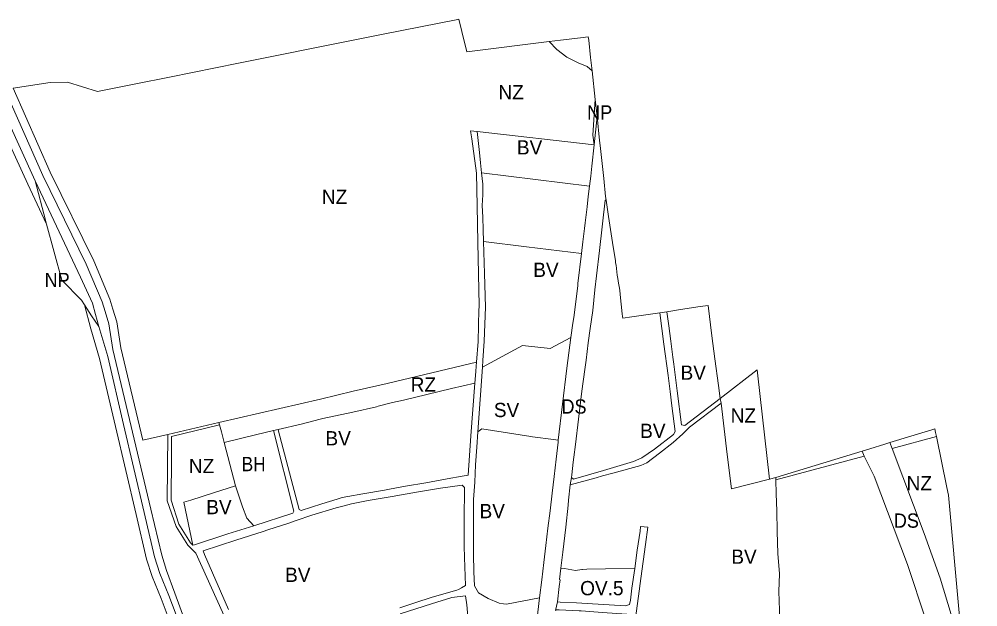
# Model space of a CAD drawing. Extents: x -650451 to -642268, y -1075216 to -1066610.
# Drawn here: x -648639 to -647831, y -1067105 to -1066610 of the extents above; entities that cross this region are included whole.
import ezdxf

# ---------------------------------------------------------------- set-up
doc = ezdxf.new("R2010")
doc.units = 0
doc.header["$LTSCALE"] = 4.8
for name, color, linetype, lineweight in [('1', 7, 'Continuous', 13), ('11', 7, 'Continuous', 13), ('15', 7, 'Continuous', 13), ('19', 7, 'Continuous', 13), ('24', 7, 'Continuous', 13), ('3', 7, 'Continuous', 13), ('45', 7, 'Continuous', 13), ('46', 7, 'Continuous', 13), ('48', 7, 'Continuous', 13), ('6', 7, 'Continuous', 13)]:
    doc.layers.add(name, color=color, linetype=linetype, lineweight=lineweight)
doc.layers.add('62', color=7, linetype='Continuous')

msp = doc.modelspace()

# ---------------------------------------------------------------- linework, layer by layer
at = {"layer": '1'}
for points in [[(-648466.26, -1066967), (-648439.91, -1066960.58), (-648424.66, -1066956.87)], [(-648424.66, -1066956.87), (-648407.6, -1067024.83), (-648408.46, -1067026.54), (-648441.28, -1067037.04)], [(-648441.28, -1067037.04), (-648447.23, -1067030.63), (-648450.92, -1067021.17), (-648456.62, -1067003.59), (-648466.26, -1066967)]]:
    msp.add_lwpolyline(points, dxfattribs=at)
at = {"layer": '11'}
for points in [[(-648185.48, -1067101.2), (-648183.92, -1067088.24), (-648183.16, -1067082.6), (-648183.67, -1067082.49), (-648182.63, -1067072.9)], [(-648120.26, -1067073.08), (-648122.67, -1067089.62), (-648123.95, -1067099.92), (-648124.74, -1067103.48), (-648128.02, -1067104.53), (-648160.45, -1067102.58), (-648169.34, -1067102.04), (-648183.06, -1067101.36), (-648185.48, -1067101.2)], [(-648182.63, -1067072.9), (-648179.46, -1067073.12), (-648170.29, -1067074.73), (-648164.79, -1067073.83), (-648164.38, -1067073.82), (-648160.6, -1067073.75), (-648144.93, -1067073.47), (-648120.26, -1067073.08)]]:
    msp.add_lwpolyline(points, dxfattribs=at)
at = {"layer": '15'}
for p, q in [((-648174.67, -1067002.55), (-648173.67, -1066996.46)), ((-648187.15, -1067108.56), (-648185.48, -1067101.2))]:
    msp.add_line(p, q, dxfattribs=at)
for points in [[(-648192.53, -1066629.28), (-648182.76, -1066628.07), (-648165.91, -1066625.97), (-648159.46, -1066625.17), (-648159.14, -1066628.07), (-648157.55, -1066642.67), (-648156.34, -1066653.83)], [(-648156.34, -1066653.83), (-648160.48, -1066650.28), (-648167.88, -1066647.1), (-648177.6, -1066642.24), (-648185.98, -1066636.03), (-648192.53, -1066629.28)], [(-648253.65, -1066899.2), (-648252.33, -1066881.94), (-648251.56, -1066854.93), (-648251.5, -1066852.88), (-648251.47, -1066851.6), (-648252.6, -1066798.46), (-648252.97, -1066767.53), (-648253.6, -1066739.98), (-648257.68, -1066711.07), (-648258.64, -1066704.31), (-648253.23, -1066704.92)], [(-648253.23, -1066704.92), (-648251.26, -1066722.82), (-648250.35, -1066731.5), (-648249.44, -1066739.8)], [(-648249.44, -1066739.8), (-648248.34, -1066749.33), (-648248.43, -1066758.34), (-648248.77, -1066767.43)], [(-648248.77, -1066767.43), (-648248.448, -1066777.212), (-648248.09, -1066787.96), (-648247.78, -1066797.53)], [(-648247.78, -1066797.53), (-648246.93, -1066824.58), (-648246.12, -1066852.86), (-648247.22, -1066881.51), (-648248.34, -1066897.92), (-648248.72, -1066903.46), (-648252.45, -1066958.01)], [(-648173.67, -1066996.46), (-648171.97, -1066997.89), (-648146.71, -1066990.48), (-648121.36, -1066982.96), (-648114.45, -1066979.9), (-648103.8, -1066972.73), (-648087.66, -1066960.29), (-648086.26, -1066957.66), (-648089.01, -1066936.01), (-648090.54, -1066924.13), (-648092.29, -1066910.62), (-648095.81, -1066884.07), (-648099.18, -1066857.71), (-648093.27, -1066856.88)], [(-648093.27, -1066856.88), (-648091.68, -1066868.78), (-648089.99, -1066881.53), (-648088.27, -1066895.01), (-648087.52, -1066900.96), (-648084.63, -1066923.32), (-648080.84, -1066952.2), (-648078.14, -1066952.77), (-648048.43, -1066929.91), (-648047.56, -1066933.82)], [(-648254.98, -1066916.96), (-648254.25, -1066907.07), (-648253.92, -1066902.78), (-648253.65, -1066899.2)], [(-648420.84, -1066956), (-648420.78, -1066956.25), (-648402.99, -1067023.54), (-648401.5, -1067024.22), (-648383.91, -1067018.53), (-648371.19, -1067014.59), (-648366.97, -1067013.34), (-648362.15, -1067012.49), (-648349.43, -1067010.23), (-648331.09, -1067007), (-648326.96, -1067006.27), (-648313.35, -1067003.85), (-648296.31, -1067000.87), (-648278.46, -1066997.56), (-648265.67, -1066995.28), (-648260.8, -1066994.4), (-648258.32, -1066961.37), (-648254.98, -1066916.96)], [(-648047.56, -1066933.82), (-648074.11, -1066953.96), (-648079.73, -1066959.7), (-648087.94, -1066966.99), (-648099.61, -1066975.99), (-648110.16, -1066984.14), (-648115.2, -1066986.34), (-648138.9, -1066992.73), (-648147.52, -1066995.06), (-648152.91, -1066996.6), (-648167.52, -1067000.71), (-648174.67, -1067002.55)], [(-648513.842, -1066960.243), (-648470.68, -1066950.24), (-648470.17, -1066952.17)], [(-648470.17, -1066952.17), (-648510.57, -1066961.9), (-648510.61, -1066966.55), (-648510.69, -1066976.8), (-648510.71, -1066978.63), (-648511.02, -1067015.58), (-648504.44, -1067035.85), (-648494.58, -1067051.41), (-648492.67, -1067053.5)], [(-648441.28, -1067037.04), (-648408.46, -1067026.54), (-648407.6, -1067024.83), (-648424.66, -1066956.87), (-648420.84, -1066956)], [(-648447.66, -1067153.25), (-648467.56, -1067110.02), (-648490.23, -1067060.06), (-648496.87, -1067053.5), (-648506.78, -1067037.81), (-648514.38, -1067016.2), (-648513.842, -1066960.243)], [(-648252.45, -1066958.01), (-648253.35, -1066970.9), (-648254.43, -1066985.75), (-648255.15, -1067000.4), (-648256.12, -1067014.87), (-648256.12, -1067029.58), (-648256.25, -1067046.57), (-648256.18, -1067061.04), (-648255.91, -1067075.83), (-648255.49, -1067087.62), (-648251.85, -1067093.58), (-648243.79, -1067098.45), (-648234.58, -1067102.41), (-648230.86, -1067102.82), (-648228.38, -1067103.09), (-648200.58, -1067097.82)], [(-648318.38, -1067106.37), (-648305.53, -1067102.05), (-648290.96, -1067097.14), (-648270.3, -1067091.29), (-648268.79, -1067090.68), (-648266.35, -1067089.33), (-648262.82, -1067087.38), (-648263.67, -1067063.83), (-648264.11, -1067054.38), (-648264, -1067049.27), (-648263.98, -1067032.43), (-648263.75, -1067004.82), (-648265.85, -1067002.98), (-648284.03, -1067005.42), (-648304.31, -1067008.7), (-648324.83, -1067012.36), (-648344.88, -1067015.79), (-648358.92, -1067018.69), (-648365.27, -1067020.27), (-648371.77, -1067022.03), (-648392.27, -1067028.16), (-648405.7, -1067032.78), (-648412.55, -1067035.13), (-648429.59, -1067040.65), (-648433.28, -1067041.85), (-648456.52, -1067049.26), (-648483.84, -1067058.1), (-648482.9, -1067061.25), (-648462.48, -1067107.73)], [(-648492.67, -1067053.5), (-648491.28, -1067053.05), (-648463.12, -1067044.04), (-648441.28, -1067037.04)], [(-648120.26, -1067073.08), (-648118.18, -1067057.64), (-648115.89, -1067041.73), (-648115.37, -1067037.82), (-648109.4, -1067038.4), (-648111.32, -1067052.86), (-648113.21, -1067067.35), (-648115.19, -1067081.63), (-648117.16, -1067096.34), (-648119.2, -1067110.85), (-648121, -1067125.08), (-648122.95, -1067140.69), (-648123.31, -1067144.17), (-648129.51, -1067143.6), (-648127.29, -1067128.4), (-648126.24, -1067112.71), (-648127.23, -1067111.47), (-648147.53, -1067110.1), (-648165.4, -1067108.88), (-648167.25, -1067108.76), (-648183.98, -1067107.89), (-648186.54, -1067107.89), (-648187.15, -1067108.56)], [(-648185.48, -1067101.2), (-648183.06, -1067101.36), (-648169.34, -1067102.04), (-648160.45, -1067102.58), (-648128.02, -1067104.53), (-648124.74, -1067103.48), (-648123.95, -1067099.92), (-648122.67, -1067089.62), (-648120.26, -1067073.08)], [(-648260.23, -1067123.43), (-648261.9, -1067103.74), (-648262.98, -1067096.21), (-648274.32, -1067097.65), (-648291.72, -1067102.95), (-648317.87, -1067111.36)], [(-648200.58, -1067097.82), (-648203.67, -1067124.43), (-648204.77, -1067124.3)]]:
    msp.add_lwpolyline(points, dxfattribs=at)
for points in [[(-647905.28, -1066967.07), (-647869.93, -1066956.27), (-647867.46, -1066955.52), (-647866.83, -1066958.62), (-647866.14, -1066961.98), (-647903.5, -1066972.05)], [(-648001.56, -1066996.48), (-647928.82, -1066974.26), (-647927.03, -1066978.39), (-648001.46, -1066998.45)]]:
    msp.add_lwpolyline(points, close=True, dxfattribs=at)
at = {"layer": '19'}
msp.add_line((-648252.45, -1066958.01), (-648248.72, -1066903.46), dxfattribs=at)
for points in [[(-648248.72, -1066903.46), (-648214.86, -1066885.27), (-648191.69, -1066887.78), (-648174.1, -1066878.6)], [(-648174.1, -1066878.6), (-648177.43, -1066904.42), (-648184.76, -1066965.08)], [(-648184.76, -1066965.08), (-648188.76, -1066964.53), (-648206.52, -1066962.1), (-648207.96, -1066961.91), (-648249.08, -1066955.37), (-648252.45, -1066958.01)]]:
    msp.add_lwpolyline(points, dxfattribs=at)
at = {"layer": '24'}
for points in [[(-648158.49, -1066750.93), (-648157.46, -1066742.51), (-648156.44, -1066734.09), (-648154.59, -1066716.19), (-648152.14, -1066692.48)], [(-648152.14, -1066692.48), (-648149.94, -1066712.67), (-648149.5, -1066716.77), (-648146.47, -1066744.59), (-648144.84, -1066759.62), (-648144.49, -1066762.87)], [(-648160.51, -1066768.4), (-648159.66, -1066759.8), (-648158.49, -1066750.93)], [(-648144.49, -1066762.87), (-648145.22, -1066762.7), (-648150.16, -1066805.32), (-648152.62, -1066826.56), (-648153.91, -1066838.34), (-648155.78, -1066855.77), (-648157.88, -1066871), (-648159.53, -1066882.99), (-648161.34, -1066897.51), (-648162.34, -1066905.6), (-648164.78, -1066923.69), (-648166.53, -1066937.71), (-648167.74, -1066947.37), (-648170.38, -1066968.61), (-648171.57, -1066979.24), (-648172.1, -1066983.53), (-648173.44, -1066994.3), (-648173.67, -1066996.46), (-648174.67, -1067002.55)], [(-648165.33, -1066807.74), (-648164.14, -1066797.98), (-648162.8, -1066786.8), (-648162.01, -1066781.79), (-648161.58, -1066777.41), (-648160.51, -1066768.4)], [(-648174.1, -1066878.6), (-648172.44, -1066866.5), (-648171.79, -1066861.74), (-648168.38, -1066834.94), (-648168.15, -1066833.1), (-648165.33, -1066807.74)], [(-648184.76, -1066965.08), (-648177.43, -1066904.42), (-648174.1, -1066878.6)], [(-648200.58, -1067097.82), (-648198.61, -1067082.61), (-648196.96, -1067068.06), (-648195.18, -1067053.61), (-648193.5, -1067039.02), (-648191.7, -1067024.43), (-648189.94, -1067009.79), (-648188.31, -1066995.56), (-648186.65, -1066980.99), (-648184.94, -1066966.58), (-648184.76, -1066965.08)], [(-647928.82, -1066974.26), (-647922.2, -1066972.24), (-647909.51, -1066968.36), (-647905.28, -1066967.07), (-647903.5, -1066972.05)], [(-647903.5, -1066972.05), (-647876.57, -1067043.5), (-647863.04, -1067081.36), (-647853.65, -1067111.91), (-647844.3, -1067141.25)], [(-647831.28, -1067280.69), (-647842.17, -1067239.18), (-647855.42, -1067190.8), (-647874.95, -1067116.23), (-647890.64, -1067069.73), (-647918.62, -1066995.29), (-647927.03, -1066978.39), (-647928.82, -1066974.26)], [(-648174.67, -1067002.55), (-648176.09, -1067015.48), (-648176.55, -1067019.65), (-648178.5, -1067038.43), (-648180.99, -1067059.37), (-648182.63, -1067072.9)], [(-648182.63, -1067072.9), (-648183.67, -1067082.49), (-648183.16, -1067082.6), (-648183.92, -1067088.24), (-648185.48, -1067101.2), (-648187.15, -1067108.56)], [(-648204.77, -1067124.3), (-648203.67, -1067124.43), (-648200.58, -1067097.82)]]:
    msp.add_lwpolyline(points, dxfattribs=at)
at = {"layer": '3'}
msp.add_line((-648253.23, -1066704.92), (-648154.59, -1066716.19), dxfattribs=at)
for points in [[(-648249.44, -1066739.8), (-648250.35, -1066731.5), (-648251.26, -1066722.82), (-648253.23, -1066704.92)], [(-648154.59, -1066716.19), (-648156.44, -1066734.09), (-648157.46, -1066742.51), (-648158.49, -1066750.93), (-648249.44, -1066739.8)], [(-648173.67, -1066996.46), (-648173.44, -1066994.3), (-648172.1, -1066983.53), (-648171.57, -1066979.24), (-648170.38, -1066968.61), (-648167.74, -1066947.37), (-648166.53, -1066937.71), (-648164.78, -1066923.69), (-648162.34, -1066905.6), (-648161.34, -1066897.51), (-648159.53, -1066882.99), (-648157.88, -1066871), (-648155.78, -1066855.77), (-648153.91, -1066838.34), (-648152.62, -1066826.56), (-648150.16, -1066805.32), (-648145.22, -1066762.7), (-648144.49, -1066762.87)], [(-648144.49, -1066762.87), (-648142.37, -1066776.69), (-648138.49, -1066802.1), (-648137.73, -1066807.04), (-648136.68, -1066813.92), (-648136.42, -1066815.56), (-648136.1, -1066817.55), (-648135.01, -1066825.88), (-648134.7, -1066828.69), (-648134.53, -1066828.66), (-648134.17, -1066831.05), (-648132.96, -1066838.67), (-648132.62, -1066842.35), (-648130.92, -1066858.62), (-648130.56, -1066860.71), (-648130.3, -1066862.19), (-648122.93, -1066861.23), (-648103.17, -1066858.32), (-648099.18, -1066857.71)], [(-648248.72, -1066903.46), (-648248.34, -1066897.92), (-648247.22, -1066881.51), (-648246.12, -1066852.86), (-648246.93, -1066824.58), (-648247.78, -1066797.53)], [(-648247.78, -1066797.53), (-648211.58, -1066802.18), (-648165.33, -1066807.74)], [(-648165.33, -1066807.74), (-648168.15, -1066833.1), (-648168.38, -1066834.94), (-648171.79, -1066861.74), (-648172.44, -1066866.5), (-648174.1, -1066878.6)], [(-648093.27, -1066856.88), (-648081.68, -1066855.07), (-648065.35, -1066852.43), (-648058.56, -1066851.51), (-648055.39, -1066877.11), (-648052.75, -1066896.43), (-648049.86, -1066918.87), (-648048.43, -1066929.91)], [(-648099.18, -1066857.71), (-648095.81, -1066884.07), (-648092.29, -1066910.62), (-648090.54, -1066924.13), (-648089.01, -1066936.01), (-648086.26, -1066957.66), (-648087.66, -1066960.29), (-648103.8, -1066972.73), (-648114.45, -1066979.9), (-648121.36, -1066982.96), (-648146.71, -1066990.48), (-648171.97, -1066997.89), (-648173.67, -1066996.46)], [(-648048.43, -1066929.91), (-648078.14, -1066952.77), (-648080.84, -1066952.2), (-648084.63, -1066923.32), (-648087.52, -1066900.96), (-648088.27, -1066895.01), (-648089.99, -1066881.53), (-648091.68, -1066868.78), (-648093.27, -1066856.88)], [(-648174.1, -1066878.6), (-648191.69, -1066887.78), (-648214.86, -1066885.27), (-648248.72, -1066903.46)], [(-648420.84, -1066956), (-648401.5, -1066951.58), (-648385.27, -1066947.45), (-648383.04, -1066946.88), (-648357.9, -1066941.49), (-648338.01, -1066936.82), (-648336.45, -1066936.45), (-648324.34, -1066933.25), (-648315.22, -1066931.2), (-648295.55, -1066926.56), (-648274.7, -1066921.51), (-648254.98, -1066916.96)], [(-648254.98, -1066916.96), (-648258.32, -1066961.37), (-648260.8, -1066994.4), (-648265.67, -1066995.28), (-648278.46, -1066997.56), (-648296.31, -1067000.87), (-648313.35, -1067003.85), (-648326.96, -1067006.27), (-648331.09, -1067007), (-648349.43, -1067010.23), (-648362.15, -1067012.49), (-648366.97, -1067013.34), (-648371.19, -1067014.59), (-648383.91, -1067018.53), (-648401.5, -1067024.22), (-648402.99, -1067023.54), (-648420.78, -1066956.25), (-648420.84, -1066956)], [(-648174.67, -1067002.55), (-648167.52, -1067000.71), (-648152.91, -1066996.6), (-648147.52, -1066995.06), (-648138.9, -1066992.73), (-648115.2, -1066986.34), (-648110.16, -1066984.14), (-648099.61, -1066975.99), (-648087.94, -1066966.99), (-648079.73, -1066959.7), (-648074.11, -1066953.96), (-648047.56, -1066933.82)], [(-648047.56, -1066933.82), (-648042.59, -1066977.18), (-648038.91, -1067006.14), (-648006.88, -1066997.86), (-648001.56, -1066996.48), (-648001.46, -1066998.45)], [(-648252.45, -1066958.01), (-648249.08, -1066955.37), (-648207.96, -1066961.91), (-648206.52, -1066962.1), (-648188.76, -1066964.53), (-648184.76, -1066965.08)], [(-648200.58, -1067097.82), (-648228.38, -1067103.09), (-648230.86, -1067102.82), (-648234.58, -1067102.41), (-648243.79, -1067098.45), (-648251.85, -1067093.58), (-648255.49, -1067087.62), (-648255.91, -1067075.83), (-648256.18, -1067061.04), (-648256.25, -1067046.57), (-648256.12, -1067029.58), (-648256.12, -1067014.87), (-648255.15, -1067000.4), (-648254.43, -1066985.75), (-648253.35, -1066970.9), (-648252.45, -1066958.01)], [(-648184.76, -1066965.08), (-648184.94, -1066966.58), (-648186.65, -1066980.99), (-648188.31, -1066995.56), (-648189.94, -1067009.79), (-648191.7, -1067024.43), (-648193.5, -1067039.02), (-648195.18, -1067053.61), (-648196.96, -1067068.06), (-648198.61, -1067082.61), (-648200.58, -1067097.82)], [(-648492.67, -1067053.5), (-648500.15, -1067017.22), (-648494.38, -1067015.42), (-648475.31, -1067009.44), (-648456.62, -1067003.59)], [(-648462.48, -1067107.73), (-648482.9, -1067061.25), (-648483.84, -1067058.1), (-648456.52, -1067049.26), (-648433.28, -1067041.85), (-648429.59, -1067040.65), (-648412.55, -1067035.13), (-648405.7, -1067032.78), (-648392.27, -1067028.16), (-648371.77, -1067022.03), (-648365.27, -1067020.27), (-648358.92, -1067018.69), (-648344.88, -1067015.79), (-648324.83, -1067012.36), (-648304.31, -1067008.7), (-648284.03, -1067005.42), (-648265.85, -1067002.98), (-648263.75, -1067004.82), (-648263.98, -1067032.43), (-648264, -1067049.27), (-648264.11, -1067054.38), (-648263.67, -1067063.83), (-648262.82, -1067087.38), (-648266.35, -1067089.33), (-648268.79, -1067090.68), (-648270.3, -1067091.29), (-648290.96, -1067097.14), (-648305.53, -1067102.05), (-648318.38, -1067106.37)], [(-648456.62, -1067003.59), (-648450.92, -1067021.17), (-648447.23, -1067030.63), (-648441.28, -1067037.04)], [(-648182.63, -1067072.9), (-648180.99, -1067059.37), (-648178.5, -1067038.43), (-648176.55, -1067019.65), (-648176.09, -1067015.48), (-648174.67, -1067002.55)], [(-648001.46, -1066998.45), (-648001.08, -1067010.1), (-648000.66, -1067024.64), (-648000.32, -1067041.95), (-647999.8, -1067060.36), (-647998.47, -1067077.62), (-647998.87, -1067092.57), (-647998.39, -1067108.26), (-647997.86, -1067123.27), (-647997.58, -1067141.08), (-648095.81, -1067160.82), (-648102.92, -1067162.24), (-648117.563, -1067165.191)], [(-648441.28, -1067037.04), (-648463.12, -1067044.04), (-648491.28, -1067053.05), (-648492.67, -1067053.5)], [(-648187.15, -1067108.56), (-648186.54, -1067107.89), (-648183.98, -1067107.89), (-648167.25, -1067108.76), (-648165.4, -1067108.88), (-648147.53, -1067110.1), (-648127.23, -1067111.47), (-648126.24, -1067112.71), (-648127.29, -1067128.4), (-648129.51, -1067143.6), (-648123.31, -1067144.17), (-648122.95, -1067140.69), (-648121, -1067125.08), (-648119.2, -1067110.85), (-648117.16, -1067096.34), (-648115.19, -1067081.63), (-648113.21, -1067067.35), (-648111.32, -1067052.86), (-648109.4, -1067038.4), (-648115.37, -1067037.82), (-648115.89, -1067041.73), (-648118.18, -1067057.64), (-648120.26, -1067073.08)], [(-648120.26, -1067073.08), (-648144.93, -1067073.47), (-648160.6, -1067073.75), (-648164.38, -1067073.82), (-648164.79, -1067073.83), (-648170.29, -1067074.73), (-648179.46, -1067073.12), (-648182.63, -1067072.9)], [(-648317.87, -1067111.36), (-648291.72, -1067102.95), (-648274.32, -1067097.65), (-648262.98, -1067096.21), (-648261.9, -1067103.74), (-648260.23, -1067123.43)]]:
    msp.add_lwpolyline(points, dxfattribs=at)
at = {"layer": '45'}
for points in [[(-648571.96, -1066869.37), (-648574.62, -1066859.15), (-648577.1, -1066849.6), (-648587.25, -1066827.6), (-648625.44, -1066746.45), (-648659.95, -1066670.89)], [(-648651.1, -1066669.56), (-648619.11, -1066742.12), (-648582.52, -1066816.7), (-648569.13, -1066848.61), (-648566.63, -1066856.72), (-648563.48, -1066866.96), (-648560.2, -1066888.58), (-648528.01, -1067023.13), (-648518.72, -1067061.99), (-648514.86, -1067074.83), (-648507.88, -1067093.9), (-648483.31, -1067160.63), (-648480.57, -1067166.13), (-648458.73, -1067229.1)], [(-648489.1, -1067158.84), (-648512.95, -1067095.97), (-648520.4, -1067077.42), (-648524.93, -1067063.35), (-648533.66, -1067026), (-648551, -1066951.85), (-648564.4, -1066894.52), (-648571.96, -1066869.37)]]:
    msp.add_lwpolyline(points, dxfattribs=at)
at = {"layer": '46'}
msp.add_line((-647903.5, -1066972.05), (-647866.14, -1066961.98), dxfattribs=at)
for points in [[(-648643.925, -1066668.483), (-648612.98, -1066663.84), (-648598.4, -1066663.4), (-648573, -1066671.24), (-648556.09, -1066667.86), (-648540.65, -1066664.77), (-648512.33, -1066659.11), (-648454.2, -1066647.48), (-648357.53, -1066628.15), (-648332.26, -1066623.09), (-648300.86, -1066616.81), (-648270.88, -1066610.82), (-648268.64, -1066610.37), (-648266.07, -1066620.89), (-648261.93, -1066637.9), (-648192.53, -1066629.28)], [(-648192.53, -1066629.28), (-648185.98, -1066636.03), (-648177.6, -1066642.24), (-648167.88, -1066647.1), (-648160.48, -1066650.28), (-648156.34, -1066653.83), (-648153.72, -1066677.95)], [(-648673.407, -1066658.275), (-648631.791, -1066749.394), (-648615.972, -1066783.008)], [(-648513.842, -1066960.243), (-648534.701, -1066965.077), (-648553.323, -1066887.238), (-648556.637, -1066865.397), (-648559.94, -1066854.66), (-648562.542, -1066846.219), (-648576.145, -1066813.802), (-648612.763, -1066739.165), (-648643.925, -1066668.483)], [(-648153.72, -1066677.95), (-648155.61, -1066708.02), (-648154.59, -1066716.19), (-648253.23, -1066704.92)], [(-648253.23, -1066704.92), (-648258.64, -1066704.31), (-648257.68, -1066711.07), (-648253.6, -1066739.98), (-648252.97, -1066767.53), (-648252.6, -1066798.46), (-648251.47, -1066851.6), (-648251.5, -1066852.88), (-648251.56, -1066854.93), (-648252.33, -1066881.94), (-648253.65, -1066899.2)], [(-648615.972, -1066783.008), (-648602.97, -1066830.11), (-648586.58, -1066847.09), (-648583.94, -1066851.11)], [(-648583.94, -1066851.11), (-648578.702, -1066871.259), (-648571.167, -1066896.326), (-648557.816, -1066953.444), (-648540.476, -1067027.594), (-648531.681, -1067065.222), (-648526.988, -1067079.8), (-648519.471, -1067098.516), (-648495.63, -1067161.363)], [(-648253.65, -1066899.2), (-648259.57, -1066900.62), (-648328.92, -1066917.33), (-648335.19, -1066918.54), (-648357.66, -1066923.74), (-648384.97, -1066930.38), (-648470.68, -1066950.24), (-648513.842, -1066960.243)], [(-648048.43, -1066929.91), (-648017.12, -1066905.83), (-648016.85, -1066908.27), (-648006.88, -1066997.86)], [(-648006.88, -1066997.86), (-648038.91, -1067006.14), (-648042.59, -1066977.18), (-648047.56, -1066933.82), (-648048.43, -1066929.91)], [(-648492.67, -1067053.5), (-648494.58, -1067051.41), (-648504.44, -1067035.85), (-648511.02, -1067015.58), (-648510.71, -1066978.63), (-648510.69, -1066976.8), (-648510.61, -1066966.55), (-648510.57, -1066961.9), (-648470.17, -1066952.17)], [(-648470.17, -1066952.17), (-648468.6, -1066958.12), (-648466.26, -1066967), (-648456.62, -1067003.59)], [(-647866.14, -1066961.98), (-647857.42, -1067004.77), (-647856.11, -1067011.21), (-647847.09, -1067110.58), (-647844.3, -1067141.25)], [(-647844.3, -1067141.25), (-647853.65, -1067111.91), (-647863.04, -1067081.36), (-647876.57, -1067043.5), (-647903.5, -1066972.05)], [(-648117.563, -1067165.191), (-648102.92, -1067162.24), (-648095.81, -1067160.82), (-647997.58, -1067141.08), (-647997.86, -1067123.27), (-647998.39, -1067108.26), (-647998.87, -1067092.57), (-647998.47, -1067077.62), (-647999.8, -1067060.36), (-648000.32, -1067041.95), (-648000.66, -1067024.64), (-648001.08, -1067010.1), (-648001.46, -1066998.45), (-647927.03, -1066978.39)], [(-647927.03, -1066978.39), (-647918.62, -1066995.29), (-647890.64, -1067069.73), (-647874.95, -1067116.23), (-647855.42, -1067190.8), (-647842.17, -1067239.18), (-647831.28, -1067280.69)], [(-648456.62, -1067003.59), (-648475.31, -1067009.44), (-648494.38, -1067015.42), (-648500.15, -1067017.22), (-648492.67, -1067053.5)]]:
    msp.add_lwpolyline(points, dxfattribs=at)
at = {"layer": '48'}
msp.add_lwpolyline([(-648154.59, -1066716.19), (-648155.61, -1066708.02), (-648153.72, -1066677.95), (-648152.14, -1066692.48)], close=True, dxfattribs=at)
for points in [[(-648625.44, -1066746.45), (-648587.25, -1066827.6), (-648577.1, -1066849.6), (-648574.62, -1066859.15), (-648571.96, -1066869.37)], [(-648615.972, -1066783.008), (-648616.86, -1066779.79), (-648625.44, -1066746.45)], [(-648583.94, -1066851.11), (-648586.58, -1066847.09), (-648602.97, -1066830.11), (-648615.972, -1066783.008)], [(-648571.96, -1066869.37), (-648577.99, -1066860.17), (-648583.94, -1066851.11)]]:
    msp.add_lwpolyline(points, dxfattribs=at)
at = {"layer": '6'}
for points in [[(-648470.68, -1066950.24), (-648384.97, -1066930.38), (-648357.66, -1066923.74), (-648335.19, -1066918.54), (-648328.92, -1066917.33), (-648259.57, -1066900.62), (-648253.65, -1066899.2)], [(-648253.65, -1066899.2), (-648253.92, -1066902.78), (-648254.25, -1066907.07), (-648254.98, -1066916.96)], [(-648254.98, -1066916.96), (-648274.7, -1066921.51), (-648295.55, -1066926.56), (-648315.22, -1066931.2), (-648324.34, -1066933.25), (-648336.45, -1066936.45), (-648338.01, -1066936.82), (-648357.9, -1066941.49), (-648383.04, -1066946.88), (-648385.27, -1066947.45), (-648401.5, -1066951.58), (-648420.84, -1066956), (-648424.66, -1066956.87)], [(-648466.26, -1066967), (-648468.6, -1066958.12), (-648470.17, -1066952.17), (-648470.68, -1066950.24)], [(-648424.66, -1066956.87), (-648439.91, -1066960.58), (-648466.26, -1066967)]]:
    msp.add_lwpolyline(points, dxfattribs=at)

# ---------------------------------------------------------------- texts
at = {"layer": '62'}
for s, p in [('NZ', (-648235.218, -1066677.958)), ('BV', (-648219.636, -1066724.365)), ('NZ', (-648383.957, -1066765.997)), ('BV', (-648205.852, -1066827.495)), ('BV', (-648081.749, -1066914.111)), ('RZ', (-648309.14, -1066924.174)), ('SV', (-648239.046, -1066945.584)), ('NZ', (-648039.517, -1066950.273)), ('BV', (-648115.782, -1066963.14)), ('BV', (-648380.935, -1066969.409)), ('NZ', (-648496.021, -1066992.771)), ('NZ', (-647891.314, -1067007.282)), ('BV', (-648481.385, -1067027.377)), ('BV', (-648251.109, -1067030.743)), ('BV', (-648038.991, -1067069.163)), ('BV', (-648414.926, -1067084.454)), ('OV.5', (-648166.342, -1067095.647))]:
    msp.add_text(s, height=12, dxfattribs=at).set_placement(p)
for s, width, p in [('NP', 0.95, (-648160.512, -1066694.934)), ('NP', 0.95, (-648617.59, -1066836.08)), ('DS', 0.95, (-648182.124, -1066942.641)), ('BH', 0.9, (-648451.457, -1066991.141)), ('DS', 0.95, (-647902.1, -1067038.771))]:
    msp.add_text(s, height=12, dxfattribs=dict(at, width=width)).set_placement(p)

doc.saveas('drawing.dxf')
